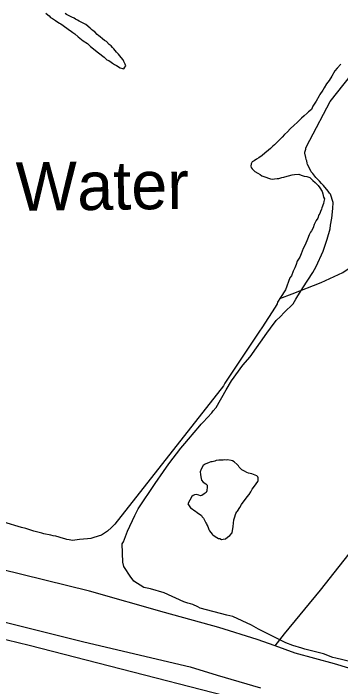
# Model space of a CAD drawing. Extents: x 3775218 to 3813389, y 343470 to 369318.
# Drawn here: x 3809383 to 3810057, y 350341 to 351727 of the extents above; entities that cross this region are included whole.
import ezdxf

# ---------------------------------------------------------------- set-up
doc = ezdxf.new("R2010")
doc.units = 0
for name, color, linetype in [('V-LEVE-TOET', 7, 'Continuous'), ('V-RIVR-IDEN', 7, 'Continuous'), ('V-SITE-VEGE', 7, 'Continuous'), ('V-TOPO-SHOR', 7, 'Continuous')]:
    doc.layers.add(name, color=color, linetype=linetype)

msp = doc.modelspace()

# ---------------------------------------------------------------- linework, layer by layer
at = {"layer": 'V-LEVE-TOET'}
msp.add_lwpolyline([(3808419.3, 350809.4), (3808640.2, 350685.3), (3808839.9, 350580.8), (3808913.8, 350550.6), (3809006.9, 350524.9), (3809415.5, 350426), (3810008, 350273.4), (3810607.5, 350115.8), (3811268, 349952.8)], dxfattribs=at)
at = {"layer": 'V-SITE-VEGE'}
msp.add_lwpolyline([(3810078.9, 350391.5), (3810047.4, 350398.9), (3810041.5, 350400.7), (3810022, 350407.9), (3809983.7, 350418), (3809977.7, 350419.9), (3809959, 350425.3), (3809944.6, 350430.7), (3809887.9, 350459.1), (3809873.5, 350467.1), (3809835.3, 350484.9), (3809822.6, 350487.7), (3809768.1, 350502.4), (3809763, 350505.1), (3809752.9, 350509.5), (3809747.8, 350511.3), (3809742.7, 350512.3), (3809734.2, 350515), (3809693.5, 350533.7), (3809665.4, 350541.9), (3809651.8, 350544.7), (3809631.5, 350557.9), (3809629.8, 350559.7), (3809624.8, 350565.8), (3809610.7, 350588.3), (3809608.3, 350596.8), (3809607.3, 350634.5), (3809609.9, 350638.7), (3809618, 350660.8), (3809633.2, 350693), (3809640.3, 350706.5), (3809675.4, 350758.9), (3809692.1, 350783.4), (3809703.5, 350799.4), (3809728.1, 350831.4), (3809736, 350841.5), (3809743.8, 350849.9), (3809767.4, 350877.7), (3809770, 350881.1), (3809774.4, 350885.3), (3809791.8, 350904.6), (3809794.5, 350908.8), (3809800.6, 350915.5), (3809821.8, 350951.9), (3809832.4, 350970.5), (3809856.1, 351002.6), (3809870.9, 351019.4), (3809905.2, 351068.3), (3809913, 351078.4), (3809924.5, 351094.5), (3809933.2, 351102.9), (3809941, 351111.3), (3809959.3, 351128.9), (3809965.4, 351138.2), (3809967.2, 351141.5), (3809979.6, 351161.8), (3809999.8, 351193.1), (3810006.9, 351205.8), (3810021.1, 351237.1), (3810024.8, 351247.3), (3810029.3, 351261.8), (3810035.7, 351283), (3810036.7, 351290.7), (3810039.5, 351305.2), (3810041.6, 351324.8), (3810041.8, 351337.6), (3810036.2, 351354.8), (3810034.5, 351356.6), (3810032, 351360.9), (3810021.9, 351372.2), (3810017.8, 351376.5), (3810013.6, 351381.7), (3810009.4, 351385.2), (3810006, 351388.7), (3810000.2, 351397.4), (3809996.8, 351400.9), (3809991.9, 351411.2), (3809989.4, 351415.5), (3809988.6, 351418.1), (3809987.8, 351423.3), (3809986.2, 351425.9), (3809985.4, 351430.1), (3809983.9, 351438.7), (3809983.9, 351441.3), (3809985.7, 351447.2), (3809985.8, 351449.8), (3809993.7, 351466), (3810036, 351545.4), (3810109.4, 351638)], dxfattribs=at)
msp.add_lwpolyline([(3809742.4, 350717.3), (3809748.2, 350708.9), (3809751.4, 350706.6), (3809755, 350704.2), (3809758.2, 350701.9), (3809761.8, 350699.5), (3809770.4, 350692.9), (3809772.2, 350690.1), (3809774.5, 350687.3), (3809778.5, 350680.3), (3809779.4, 350678), (3809780.7, 350676.1), (3809781.6, 350673.8), (3809783.4, 350670.6), (3809786, 350664.1), (3809787.3, 350661.3), (3809792.3, 350654.8), (3809794.1, 350652.9), (3809799.1, 350650), (3809805.9, 350645.8), (3809808.2, 350645.3), (3809811.8, 350643.8), (3809815.1, 350644.2), (3809820.1, 350645.1), (3809823.9, 350648.7), (3809829, 350651.8), (3809833.7, 350657.2), (3809835.8, 350670.1), (3809837.4, 350684.3), (3809838.4, 350688.4), (3809841.3, 350697.1), (3809843.7, 350700.3), (3809844.6, 350702.1), (3809849.4, 350709.3), (3809853.2, 350715.7), (3809864.5, 350731.1), (3809868.7, 350736.1), (3809872.1, 350742), (3809875.4, 350747), (3809880.1, 350753.4), (3809886.7, 350762.9), (3809887.2, 350765.2), (3809887.3, 350770.3), (3809886.9, 350772.6), (3809884.6, 350774.9), (3809874.1, 350778.8), (3809867.7, 350780.3), (3809864.1, 350781.7), (3809859, 350784.1), (3809853.6, 350787), (3809851.8, 350788.9), (3809848.6, 350792.6), (3809846.8, 350795.4), (3809844.1, 350798.2), (3809837.8, 350803.4), (3809834.6, 350805.3), (3809831.9, 350806.2), (3809824.1, 350807.3), (3809821.8, 350806.9), (3809818.1, 350807.4), (3809815.3, 350807), (3809806.1, 350807.2), (3809801.1, 350806.4), (3809797.8, 350805), (3809792.3, 350803.8), (3809790, 350803.3), (3809786.3, 350802), (3809777.9, 350798.5), (3809774.2, 350795.8), (3809769.9, 350788.1), (3809768, 350782.6), (3809768.3, 350777.1), (3809769.2, 350772.9), (3809770.9, 350765.5), (3809774, 350761.8), (3809779.5, 350758), (3809782.2, 350755.2), (3809782.6, 350752), (3809781.5, 350743.7), (3809780.1, 350740.5), (3809778.2, 350738.7), (3809775.9, 350737.4), (3809771.2, 350734.3), (3809768.9, 350733.4), (3809764.8, 350734.8), (3809759.7, 350735.9), (3809756.5, 350735.5), (3809753.3, 350734.1), (3809750.9, 350732.3)], close=True, dxfattribs=at)
at = {"layer": 'V-TOPO-SHOR'}
for points in [[(3809932.2, 351139.9), (3809957.2, 351149.5), (3810017.4, 351172.9), (3810062, 351193.1), (3810076.8, 351203.6), (3810088, 351215.9), (3810098.3, 351227.4), (3810109.9, 351240.8), (3810128.3, 351275.2), (3810163.5, 351338.7), (3810207, 351392.5), (3810292.5, 351501), (3810374.5, 351602.2), (3810447.4, 351692.5), (3810517.6, 351780.7), (3810616.6, 351903.2), (3810707.8, 352017.5), (3810783, 352112.6), (3810842, 352185.9), (3810885.9, 352239.5)], [(3809449.8, 351727.5), (3809453.6, 351723.6), (3809456.5, 351721.6), (3809459.3, 351718.6), (3809463.2, 351716.6), (3809470, 351712.5), (3809474.8, 351708.5), (3809477.7, 351706.5), (3809480.6, 351705.5), (3809493.1, 351696.5), (3809496, 351694.5), (3809502.7, 351689.5), (3809505.6, 351687.5), (3809509.4, 351684.5), (3809516.2, 351678.5), (3809520, 351675.5), (3809526.7, 351670.5), (3809535.4, 351664.5), (3809542.1, 351658.5), (3809558.5, 351645.5), (3809570, 351636.5), (3809575.8, 351631.5), (3809579.6, 351629.5), (3809584.5, 351626.5), (3809587.3, 351624.5), (3809591.2, 351621.5), (3809595.1, 351619.5), (3809602.8, 351614.5), (3809607.6, 351613.4), (3809610.5, 351612.4), (3809612.6, 351616.2), (3809614.6, 351619.1), (3809613.6, 351622.1), (3809610.8, 351628), (3809608.9, 351630.9), (3809605.1, 351635.9), (3809599.4, 351642.8), (3809595.6, 351646.8), (3809589.8, 351653.7), (3809587, 351656.7), (3809584.1, 351659.7), (3809580.3, 351662.7), (3809574.5, 351668.6), (3809570.6, 351670.7), (3809566.8, 351674.6), (3809562, 351678.6), (3809559.1, 351680.6), (3809555.3, 351683.6), (3809550.5, 351688.6), (3809547.6, 351690.6), (3809543.8, 351693.6), (3809540.9, 351696.6), (3809532.2, 351703.6), (3809529.3, 351705.6), (3809525.5, 351707.6), (3809518.7, 351710.6), (3809514.8, 351712.7), (3809511, 351714.7), (3809508.1, 351716.7), (3809503.3, 351718.7), (3809496.5, 351722.8), (3809492.6, 351724.8), (3809489.7, 351726.8)], [(3810057.5, 351622.6), (3810050.5, 351613.9), (3810045.6, 351608.2), (3810039.5, 351597.6), (3810033.5, 351588.9), (3810028.5, 351582.1), (3810023.5, 351573.5), (3810020.4, 351568.6), (3810014.4, 351560), (3810013.4, 351557.1), (3810007.3, 351546.4), (3810000.3, 351535.8), (3809997.3, 351529.1), (3809991.3, 351524.3), (3809988.3, 351521.4), (3809982.4, 351515.7), (3809976.4, 351510.9), (3809967.5, 351502.3), (3809961.5, 351496.6), (3809953.6, 351488.9), (3809947.6, 351483.2), (3809941.7, 351477.4), (3809936.7, 351471.7), (3809933.7, 351468.8), (3809929.7, 351465), (3809923.8, 351459.2), (3809920.8, 351456.4), (3809917.8, 351453.5), (3809912.8, 351448.7), (3809908.9, 351444.9), (3809901, 351439.2), (3809896, 351434.4), (3809889.1, 351429.6), (3809884.1, 351426.8), (3809879.2, 351423), (3809875.3, 351421.1), (3809873.2, 351417.2), (3809872.2, 351412.4), (3809873.1, 351409.4), (3809875, 351406.5), (3809880.7, 351401.5), (3809886.5, 351397.5), (3809891.4, 351395.4), (3809895.2, 351392.4), (3809903, 351389.4), (3809908.8, 351387.3), (3809912.7, 351386.3), (3809917.5, 351385.2), (3809921.4, 351386.1), (3809926.3, 351387), (3809930.2, 351386.9), (3809936.1, 351388.8), (3809940, 351389.7), (3809946.9, 351391.5), (3809949.8, 351392.4), (3809957.7, 351394.2), (3809962.6, 351395.1), (3809971.4, 351395.9), (3809976.2, 351393.9), (3809982, 351391.8), (3809987.9, 351390.7), (3809993.7, 351388.7), (3810000.4, 351382.7), (3810005.2, 351378.7), (3810010.9, 351372.7), (3810014.7, 351367.8), (3810019.5, 351359.9), (3810020.4, 351355), (3810022.2, 351348.1), (3810024.1, 351345.2), (3810023, 351339.3), (3810022, 351335.5), (3810018.9, 351326.7), (3810017.8, 351323.8), (3810015.8, 351319), (3810014.7, 351315.1), (3810012.7, 351312.2), (3810010.7, 351305.4), (3810006.7, 351300.6), (3810002.6, 351291.9), (3810000.5, 351285.1), (3809997.5, 351279.3), (3809995.5, 351276.4), (3809992.5, 351270.6), (3809989.4, 351261.9), (3809984.3, 351250.3), (3809980.2, 351242.6), (3809976.1, 351231.9), (3809973.1, 351225.1), (3809968, 351216.5), (3809966, 351209.7), (3809962.9, 351202.9), (3809959.9, 351196.1), (3809955.8, 351186.4), (3809952.8, 351182.6)], [(3809922.2, 350424.5), (3809941.7, 350449.6), (3810016, 350539.1), (3810092.9, 350636.8), (3810179.9, 350746.4), (3810291.1, 350887.6), (3810415.4, 351042.5), (3810521.5, 351175.2), (3810648, 351333.7), (3810784.9, 351500.9), (3810837.4, 351563.7)], [(3809952.8, 351182.6), (3809943.5, 351157.4), (3809933.5, 351142), (3809927.4, 351132.3), (3809926.4, 351128.5), (3809922.4, 351121.7), (3809895.2, 351079.3), (3809890.2, 351072.5), (3809819, 350965.6), (3809815.9, 350959.8), (3809592.1, 350675.2), (3809585.2, 350668.5), (3809577.2, 350660.8), (3809564.4, 350652.3), (3809548.7, 350647.7), (3809542.8, 350645.9), (3809536, 350645), (3809519.3, 350643.4), (3809504.7, 350641.7), (3809497.9, 350642.8), (3809493, 350643.9), (3809489.1, 350644.9), (3809486.2, 350645.9), (3809470.7, 350650.1)], [(3809885.3, 350437.9), (3809806.6, 350462.6), (3809694.1, 350493.5), (3809540.1, 350537.5), (3809355.9, 350582.7), (3809328.4, 350589.3), (3809167.3, 350627.9), (3809005.4, 350671.7), (3808891.5, 350702.2), (3808849.2, 350720.4), (3808767.7, 350756.4), (3808684, 350803.9), (3808601.7, 350864.1), (3808460.5, 350951.9), (3808400.1, 350995.4)], [(3808396.7, 350878.7), (3808500.1, 350810.8), (3808584.6, 350755.1), (3808657.2, 350705.8), (3808719.3, 350668.5), (3808781.6, 350638.1), (3808814.9, 350622), (3808834.7, 350614.1), (3808854.8, 350607.5), (3808874.9, 350601.2), (3808893.8, 350597.2), (3809054.4, 350554.4), (3809323.8, 350483.7), (3809528.2, 350432.6), (3809747.3, 350381.7), (3809803.2, 350364.2), (3809892.1, 350338)], [(3809470.7, 350650.1), (3809464.9, 350651.2), (3809460, 350652.3), (3809445.4, 350655.5), (3809441.5, 350656.5), (3809425, 350660.7), (3809421.2, 350661.8), (3809408.5, 350665.9), (3809399.8, 350668), (3809363, 350679.4)], [(3811266, 350088.1), (3811126, 350122.1), (3810999.4, 350149.2), (3810870.3, 350169.4), (3810829, 350177.5), (3810757.3, 350194.3), (3810648.8, 350225.6), (3810475.2, 350273.7), (3810439.2, 350282.4), (3810317.4, 350313.1), (3810188.3, 350344.4), (3810133.3, 350360.9), (3810044.6, 350387.4), (3809963.9, 350409.3), (3809922.2, 350424.5), (3809885.3, 350437.9)]]:
    msp.add_lwpolyline(points, dxfattribs=at)

# ---------------------------------------------------------------- texts
at = {"layer": 'V-RIVR-IDEN'}
msp.add_text('Water', height=100, rotation=0.7588, dxfattribs=at).set_placement((3809388.7, 351319.9))

doc.saveas('drawing.dxf')
